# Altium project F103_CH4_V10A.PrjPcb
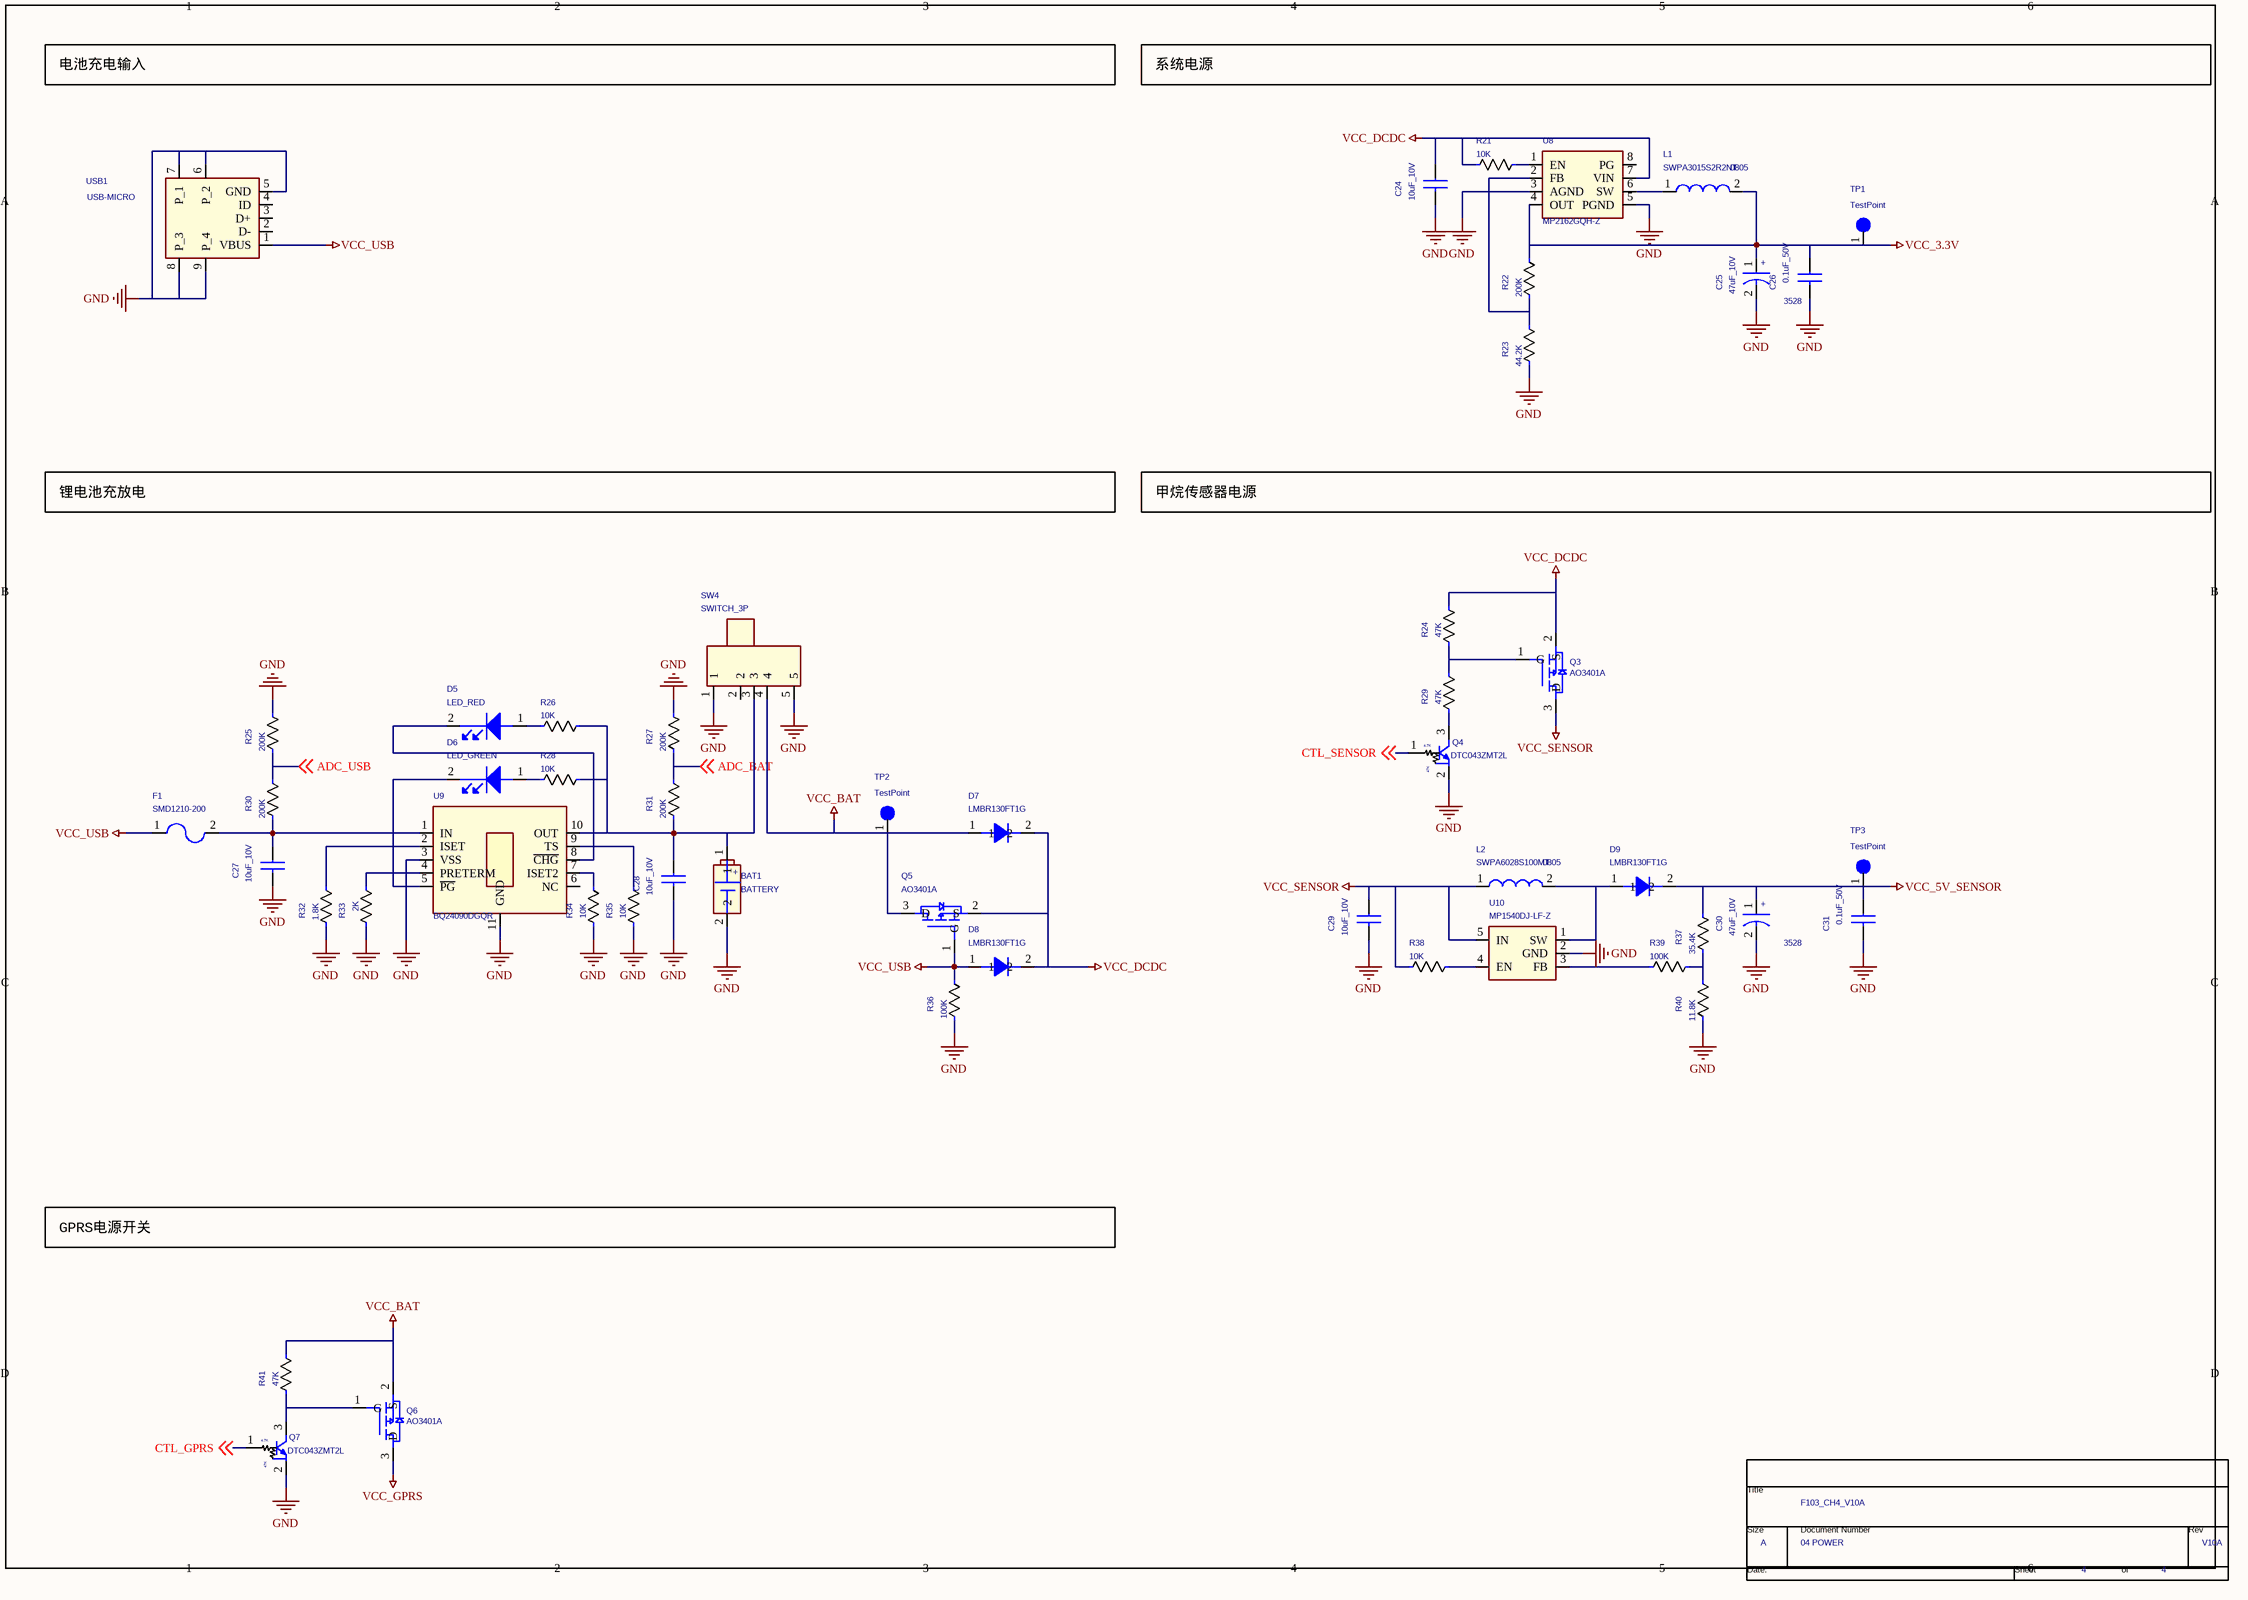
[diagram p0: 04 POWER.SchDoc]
4 sheets, 120 parts. Net scope: global (net labels, ports and power ports of the same name join across sheets).
Board file: F103_CH4_V10A.PcbDoc
Sheets:
  04 POWER.SchDoc
  03 GPRS.SchDoc
  02 MCU&SENSOR.SchDoc
  01 COVER.SchDoc

## Sheet 04 POWER.SchDoc
size 420 x 297 mm

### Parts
(Parts that share a designator on the sheet are numbered #1, #2 ... from top to bottom, then left to right.)
*#1  Page Count: 4  Page Size: A  Title: F103_CH4_V10A  RevCode: V10A  Doc: 04 POWER  (hidden comment: TitleBlock0)  (graphical)
BAT1  BATTERY  [BATTERY]
C24  10uF_10V  [C0603]
C25  47uF_10V  Shape: 3528  [CT_3528_IPC]
C26  0.1uF_50V  [C0603]
C27  10uF_10V  [C0603]
C28  10uF_10V  [C0603]
C29  10uF_10V  [C0603]
C30  47uF_10V  Shape: 3528  [CT_3528_IPC]
C31  0.1uF_50V  [C0603]
D5  LED_RED  [LED0805]
D6  LED_GREEN  [LED0805]
D7  LMBR130FT1G  [SOD123]
D8  LMBR130FT1G  [SOD123]
D9  LMBR130FT1G  [SOD123]
F1  SMD1210-200  [SMD-2920]
L1  SWPA3015S2R2NT  Shape: 0805  [L_0805_IPC]
L2  SWPA6028S100MT  Shape: 0805  [L_0805_IPC]
Q3  AO3401A  [SOT23_GSD]
Q4  DTC043ZMT2L  [SOT-723]
Q5  AO3401A  [SOT23_GSD]
Q6  AO3401A  [SOT23_GSD]
Q7  DTC043ZMT2L  [SOT-723]
R21  10K  [R0603]
R22  200K  [R0603]
R23  44.2K  [R0603]
R24  47K  [R0603]
R25  200K  [R0603]
R26  10K  [R0603]
R27  200K  [R0603]
R28  10K  [R0603]
R29  47K  [R0603]
R30  200K  [R0603]
R31  200K  [R0603]
R32  1.8K  [R0603]
R33  2K  [R0603]
R34  10K  [R0603]
R35  10K  [R0603]
R36  100K  [R0603]
R37  35.4K  [R0603]
R38  10K  [R0603]
R39  100K  [R0603]
R40  11.8K  [R0603]
R41  47K  [R0603]
SW4  SWITCH_3P  [SWITCH_3P]
TP1  TestPoint  [TP-0R75]
TP2  TestPoint  [TP-0R75]
TP3  TestPoint  [TP-0R75]
U8  MP2162GQH-Z  [QFN-8]
U9  BQ24090DGQR  [HVSSOP-10]
U10  MP1540DJ-LF-Z  [TSOT23-5]
USB1  USB-MICRO  [MICROUSB]

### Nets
GND: BAT1.2 C24.2 C25.2 C26.2 C27.2 C28.2 C29.2 C30.2 C31.2 Q4.2 Q7.2 R23.2 R25.1 R27.1 R32.2 R33.2 R34.2 R35.2 R36.2 R40.2 SW4.1 SW4.5 U8.3(AGND) U8.5(PGND) U9.3(VSS) U9.11(GND) U10.2(GND) USB1.5(GND) USB1.6(P_2) USB1.7(P_1) USB1.8(P_3) USB1.9(P_4)
VCC_3.3V: C25.1 C26.1 L1.2(B) R22.1 TP1.1 U8.4(OUT)
VCC_5V_SENSOR: C30.1 C31.1 D9.2 R37.1 TP3.1
VCC_BAT: D7.1 Q5.3(D) Q6.2(S) R41.1 SW4.4 TP2.1
VCC_DCDC: C24.1 D7.2 D8.2 Q3.2(S) Q5.2(S) R21.1 R24.1 U8.7(VIN)
VCC_GPRS: Q6.3(D)
VCC_SENSOR: C29.1 L2.1(A) Q3.3(D) R38.1 U10.5(IN)
VCC_USB: D8.1 F1.1 Q5.1(G) R36.1 USB1.1(VBUS)
ADC_BAT: R27.2 R31.1 ; off-sheet ADC_BAT
ADC_USB: R25.2 R30.1 ; off-sheet ADC_USB
CTL_GPRS: Q7.1 ; off-sheet CTL_GPRS
CTL_SENSOR: Q4.1 ; off-sheet CTL_SENSOR
NetBAT1_1: BAT1.1 C28.1 R26.2 R28.2 R31.2 SW4.3 U9.10(OUT)
NetC27_1: C27.1 F1.2 R30.2 U9.1(IN)
NetD5_1: D5.1(ANODE) R26.1
NetD5_2: D5.2(CATHODE) U9.8(~{CHG})
NetD6_1: D6.1(ANODE) R28.1
NetD6_2: D6.2(CATHODE) U9.5(~{PG})
NetD9_1: D9.1 L2.2(B) U10.1(SW)
NetL1_1: L1.1(A) U8.6(SW)
NetQ3_1: Q3.1(G) R24.2 R29.1
NetQ4_3: Q4.3 R29.2
NetQ6_1: Q6.1(G) Q7.3 R41.2
NetR21_2: R21.2 U8.1(EN)
NetR22_2: R22.2 R23.1 U8.2(FB)
NetR32_1: R32.1 U9.2(ISET)
NetR33_1: R33.1 U9.4(PRETERM)
NetR34_1: R34.1 U9.7(ISET2)
NetR35_1: R35.1 U9.9(TS)
NetR37_2: R37.2 R39.2 R40.1
NetR38_2: R38.2 U10.4(EN)
NetR39_1: R39.1 U10.3(FB)

Not connected (* = marked no-connect by the designer): SW4 2; U8 8(PG); U9 6(NC); USB1 2(D-) 3(D+) 4(ID)

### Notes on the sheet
- 电池充电输入
- 系统电源
- 锂电池充放电
- 甲烷传感器电源
- GPRS电源开关

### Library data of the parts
BAT1 = BATTERY: XHB-2A
C24 C27-C29 = CAP NP_2: CAP,CERM,+/-10%,X7R,0603; Corporation: FH
C25 C30 = TMP_154254: CAP,TAN,TAJB476K010RNJ; Corporation: AVX; GRN: LHR; EP#: P10100000000041; MFGI 2#: KEM: T494B107K006ATH; MFGI 1#: AVX: TPSB107K006R; Board Option: Base
C26 C31 = CAP NP_Dup1: CAP,CERM,50V,+/-10%,X7R,0603; Corporation: FH
D5 = LED_4: LED; vend_part_desc: DIGI-KEY;PANASONIC; Vend_part_no: P525CT-ND;LNJ308G8TRA; BRCMPN: 106336-00; Second_Description: SING DIF; Vendor_Name: DIGI-KEY;VENDOR TO BE DETERMINED; Specs: 0603
D6 = LED_4: LED; BRCMPN: 106336-00; Vend_part_no: P525CT-ND;LNJ308G8TRA; vend_part_desc: DIGI-KEY;PANASONIC; Description 2: SING DIF; Specs: 0603; Vendor_Name: DIGI-KEY;VENDOR TO BE DETERMINED
D7-D9 = DIODE13_0: SURFACE MOUNT SCHOTTKY BARRIER RECTIFIER; Type: DIODE; Corporation: LRC
F1 = FUSE: Corporation: BOURNS
L1 L2 = IND_BEAD_0805_600OHM_1: MFGI 2#: TDK: MMZ2012Y601B; MFGI 1#: MUR: BLM21B601SPT; Board Option: Base; EP#: P11000000000010; GRN: LHR; Corporation: SUNLORD; Type: INDUCTOR
Q3 Q6 = MOS-P_0_Dup1: 30V P-Channel MOSFET; Corporation: AOS; Type: MOS
Q4 Q7 = DTC043ZMT2L: Corporation: ROHM; Type: NPN
Q5 = MOS-P: 30V P-Channel MOSFET; Corporation: AOS; Type: MOS
R21-R41 = R_Generic: RES,1%,0.1W,0603; Mfg #1: KOA SPEER; P/N #1: RK73H1JT1002F; P/N #3: CR10-103J-T; Corporation: FH
TP1-TP3 = TestPoint_0: Note: NI
U8 = MP2162GQH-Z: 2A, 6V, 1.5MHz SYNCHRONOUS STEP-DOWN SWITCHER; Corporation: MPS
U9 = BQ24090: 1A, Single-Input, Single Cell Li-Ion and Li-Pol Battery Charger; Corporation: TI
U10 = MP1540DJ-LF-Z: 1.3MHz, 18V STEP-UP CONVERTER; Corporation: MPS
USB1 = USB-MICRO: Corporation: LC

## Sheet 03 GPRS.SchDoc
size 420 x 297 mm
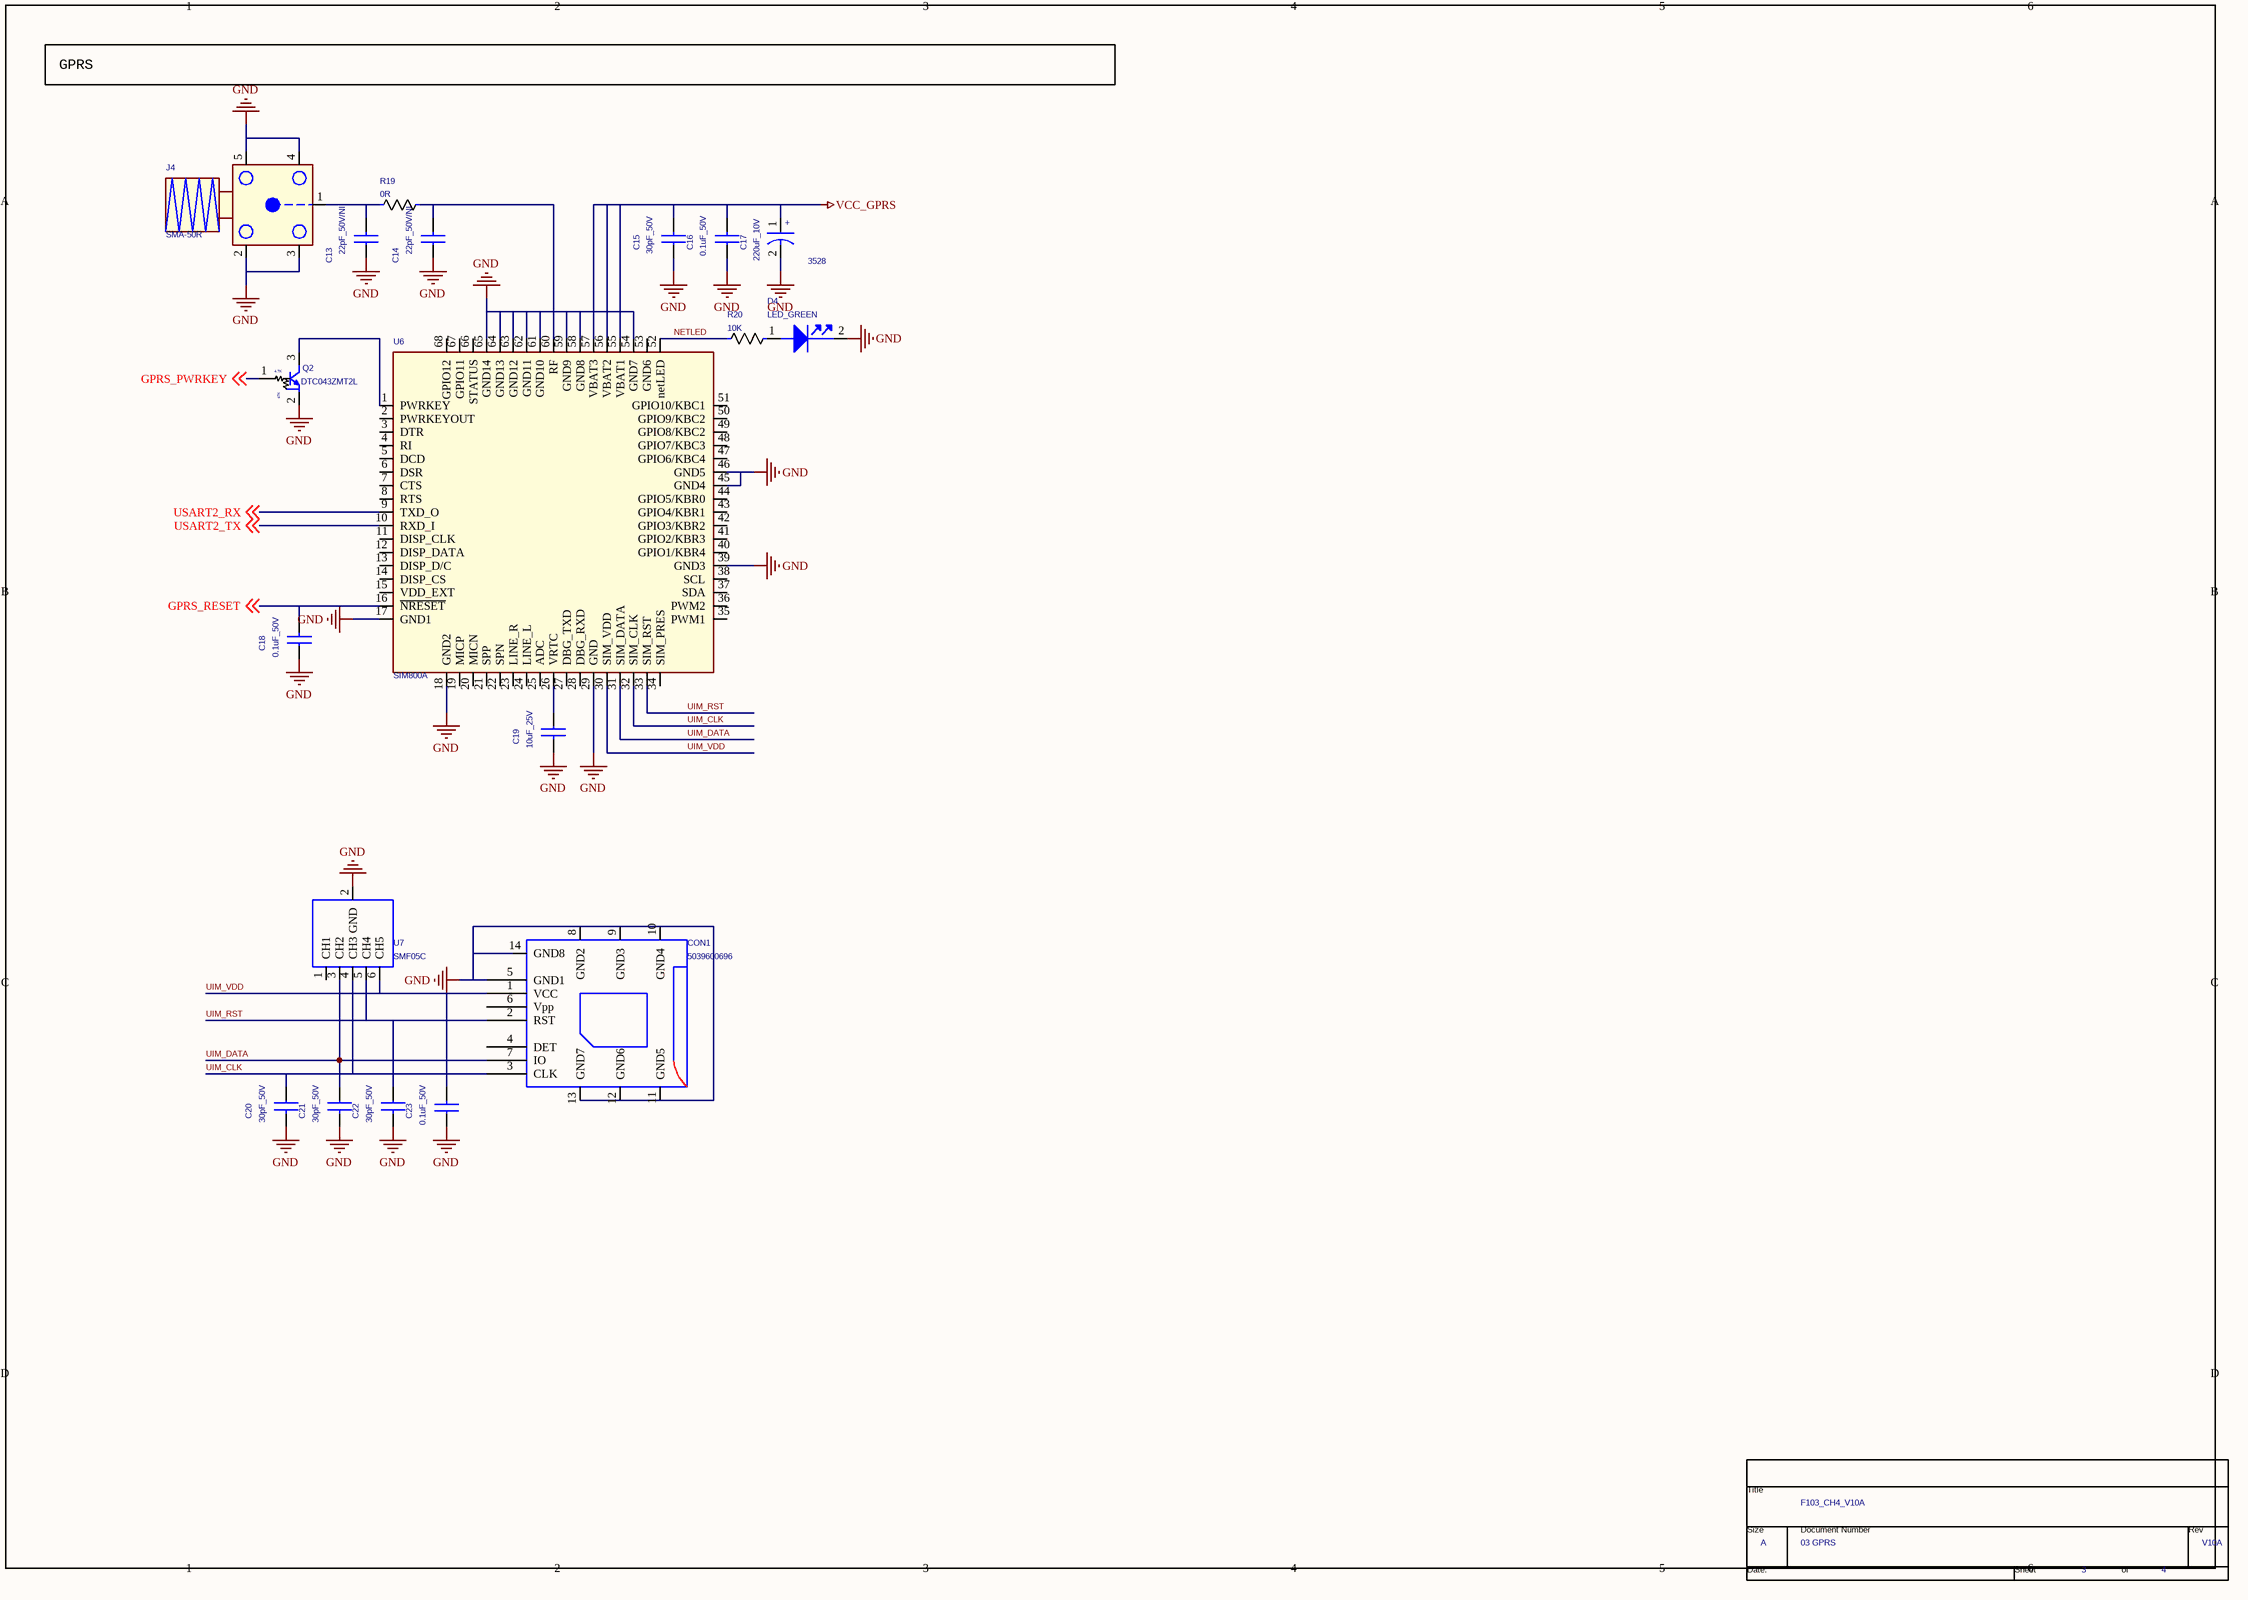
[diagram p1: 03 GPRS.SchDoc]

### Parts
(Parts that share a designator on the sheet are numbered #1, #2 ... from top to bottom, then left to right.)
*#2  Page Count: 4  Page Number: 3  Page Size: A  Title: F103_CH4_V10A  RevCode: V10A  Doc: 03 GPRS  (hidden comment: TitleBlock0)  (graphical)
C13  22pF_50V/NI  [C0603]
C14  22pF_50V/NI  [C0603]
C15  30pF_50V  [C0603]
C16  0.1uF_50V  [C0603]
C17  220uF_10V  Shape: 3528  [CT_3528_IPC]
C18  0.1uF_50V  [C0603]
C19  10uF_25V  [C0805]
C20  30pF_50V  [C0603]
C21  30pF_50V  [C0603]
C22  30pF_50V  [C0603]
C23  0.1uF_50V  [C0603]
CON1  5039600696  [SIM_PUSH]
D4  LED_GREEN  [LED0805]
J4  SMA-50R  [SMA-50R]
Q2  DTC043ZMT2L  [SOT-723]
R19  0R  [R0603]
R20  10K  [R0603]
U6  SIM800A  [SIM800A]
U7  SMF05C  [SOT363]

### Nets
GND: C13.1 C14.1 C15.1 C16.1 C17.2 C18.1 C19.2 C20.2 C21.2 C22.2 C23.1 CON1.5(GND1) CON1.8(GND2) CON1.9(GND3) CON1.10(GND4) CON1.11(GND5) CON1.12(GND6) CON1.13(GND7) CON1.14(GND8) D4.2(CATHODE) J4.2 J4.3 J4.4 J4.5 Q2.2 U6.17(GND1) U6.18(GND2) U6.29(GND) U6.39(GND3) U6.45(GND4) U6.46(GND5) U6.54(GND7) U6.58(GND8) U6.59(GND9) U6.61(GND10) U6.62(GND11) U6.63(GND12) U6.64(GND13) U6.65(GND14) U7.2(GND)
VCC_GPRS: C15.2 C16.2 C17.1 U6.55(VBAT1) U6.56(VBAT2) U6.57(VBAT3)
GPRS_PWRKEY: Q2.1 ; off-sheet GPRS_PWRKEY
GPRS_RESET: C18.2 U6.16(~{NRESET}) ; off-sheet GPRS_RESET
NETLED: R20.1 U6.52(netLED)
UIM_CLK: C20.1 CON1.3(CLK) U6.32(SIM_CLK) U7.4(CH3)
UIM_DATA: C21.1 CON1.7(IO) U6.31(SIM_DATA) U7.3(CH2)
UIM_RST: C22.1 CON1.2(RST) U6.33(SIM_RST) U7.5(CH4)
UIM_VDD: C23.2 CON1.1(VCC) U6.30(SIM_VDD) U7.6(CH5)
USART2_RX: U6.9(TXD_O) ; off-sheet USART2_RX
USART2_TX: U6.10(RXD_I) ; off-sheet USART2_TX
NetC13_2: C13.2 J4.1 R19.1
NetC14_2: C14.2 R19.2 U6.60(RF)
NetC19_1: C19.1 U6.26(VRTC)
NetD4_1: D4.1(ANODE) R20.2
NetQ2_3: Q2.3 U6.1(PWRKEY)

Not connected (* = marked no-connect by the designer): CON1 4(DET) 6(Vpp); U6 2(PWRKEYOUT) 3(DTR) 4(RI) 5(DCD) 6(DSR) 7(CTS) 8(RTS) 11(DISP_CLK) 12(DISP_DATA) 13(DISP_D/C) 14(DISP_CS) 15(VDD_EXT) 19(MICP) 20(MICN) 21(SPP) 22(SPN) 23(LINE_R) 24(LINE_L) 25(ADC) 27(DBG_TXD) 28(DBG_RXD) 34(SIM_PRES) 35(PWM1) 36(PWM2) 37(SDA) 38(SCL) 40(GPIO1/KBR4) 41(GPIO2/KBR3) 42(GPIO3/KBR2) 43(GPIO4/KBR1) 44(GPIO5/KBR0) 47(GPIO6/KBC4) 48(GPIO7/KBC3) 49(GPIO8/KBC2) 50(GPIO9/KBC2) 51(GPIO10/KBC1) 53(GND6) 66(STATUS) 67(GPIO11) 68(GPIO12); U7 1(CH1)

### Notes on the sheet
- GPRS

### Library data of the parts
C13-C16 C18 C20-C23 = CAP NP_2: as C24 on sheet 04 POWER
C17 = TMP_154254: CAP,TAN,TAJE227M010RNJ; Corporation: AVX; GRN: LHR; EP#: P10100000000041; MFGI 2#: KEM: T494B107K006ATH; MFGI 1#: AVX: TPSB107K006R; Board Option: Base
C19 = CAP NP_0: CAP,CERM,+/-10%,X5R,0805; Corporation: FH
CON1 = SIM_Card_2: SIM_PUSH; Corporation: MOLEX
D4 = LED_4: vend_part_desc: DIGI-KEY;PANASONIC; Vend_part_no: P525CT-ND;LNJ308G8TRA; BRCMPN: 106336-00; Second_Description: SING DIF; Vendor_Name: DIGI-KEY;VENDOR TO BE DETERMINED; Specs: 0603; Type: LED
J4 = SMA-50R_0: SMA-50R-DIP
Q2 = DTC043ZMT2L: Corporation: ROHM; Type: NPN
R19 R20 = R_Generic: as R21 on sheet 04 POWER
U6 = SIM800A: GPRS MODULA; Corporation: SIMCOM
U7 = SMF05CT1G: 5-Line TVS Array; Corporation: ON

## Sheet 02 MCU&SENSOR.SchDoc
size 420 x 297 mm
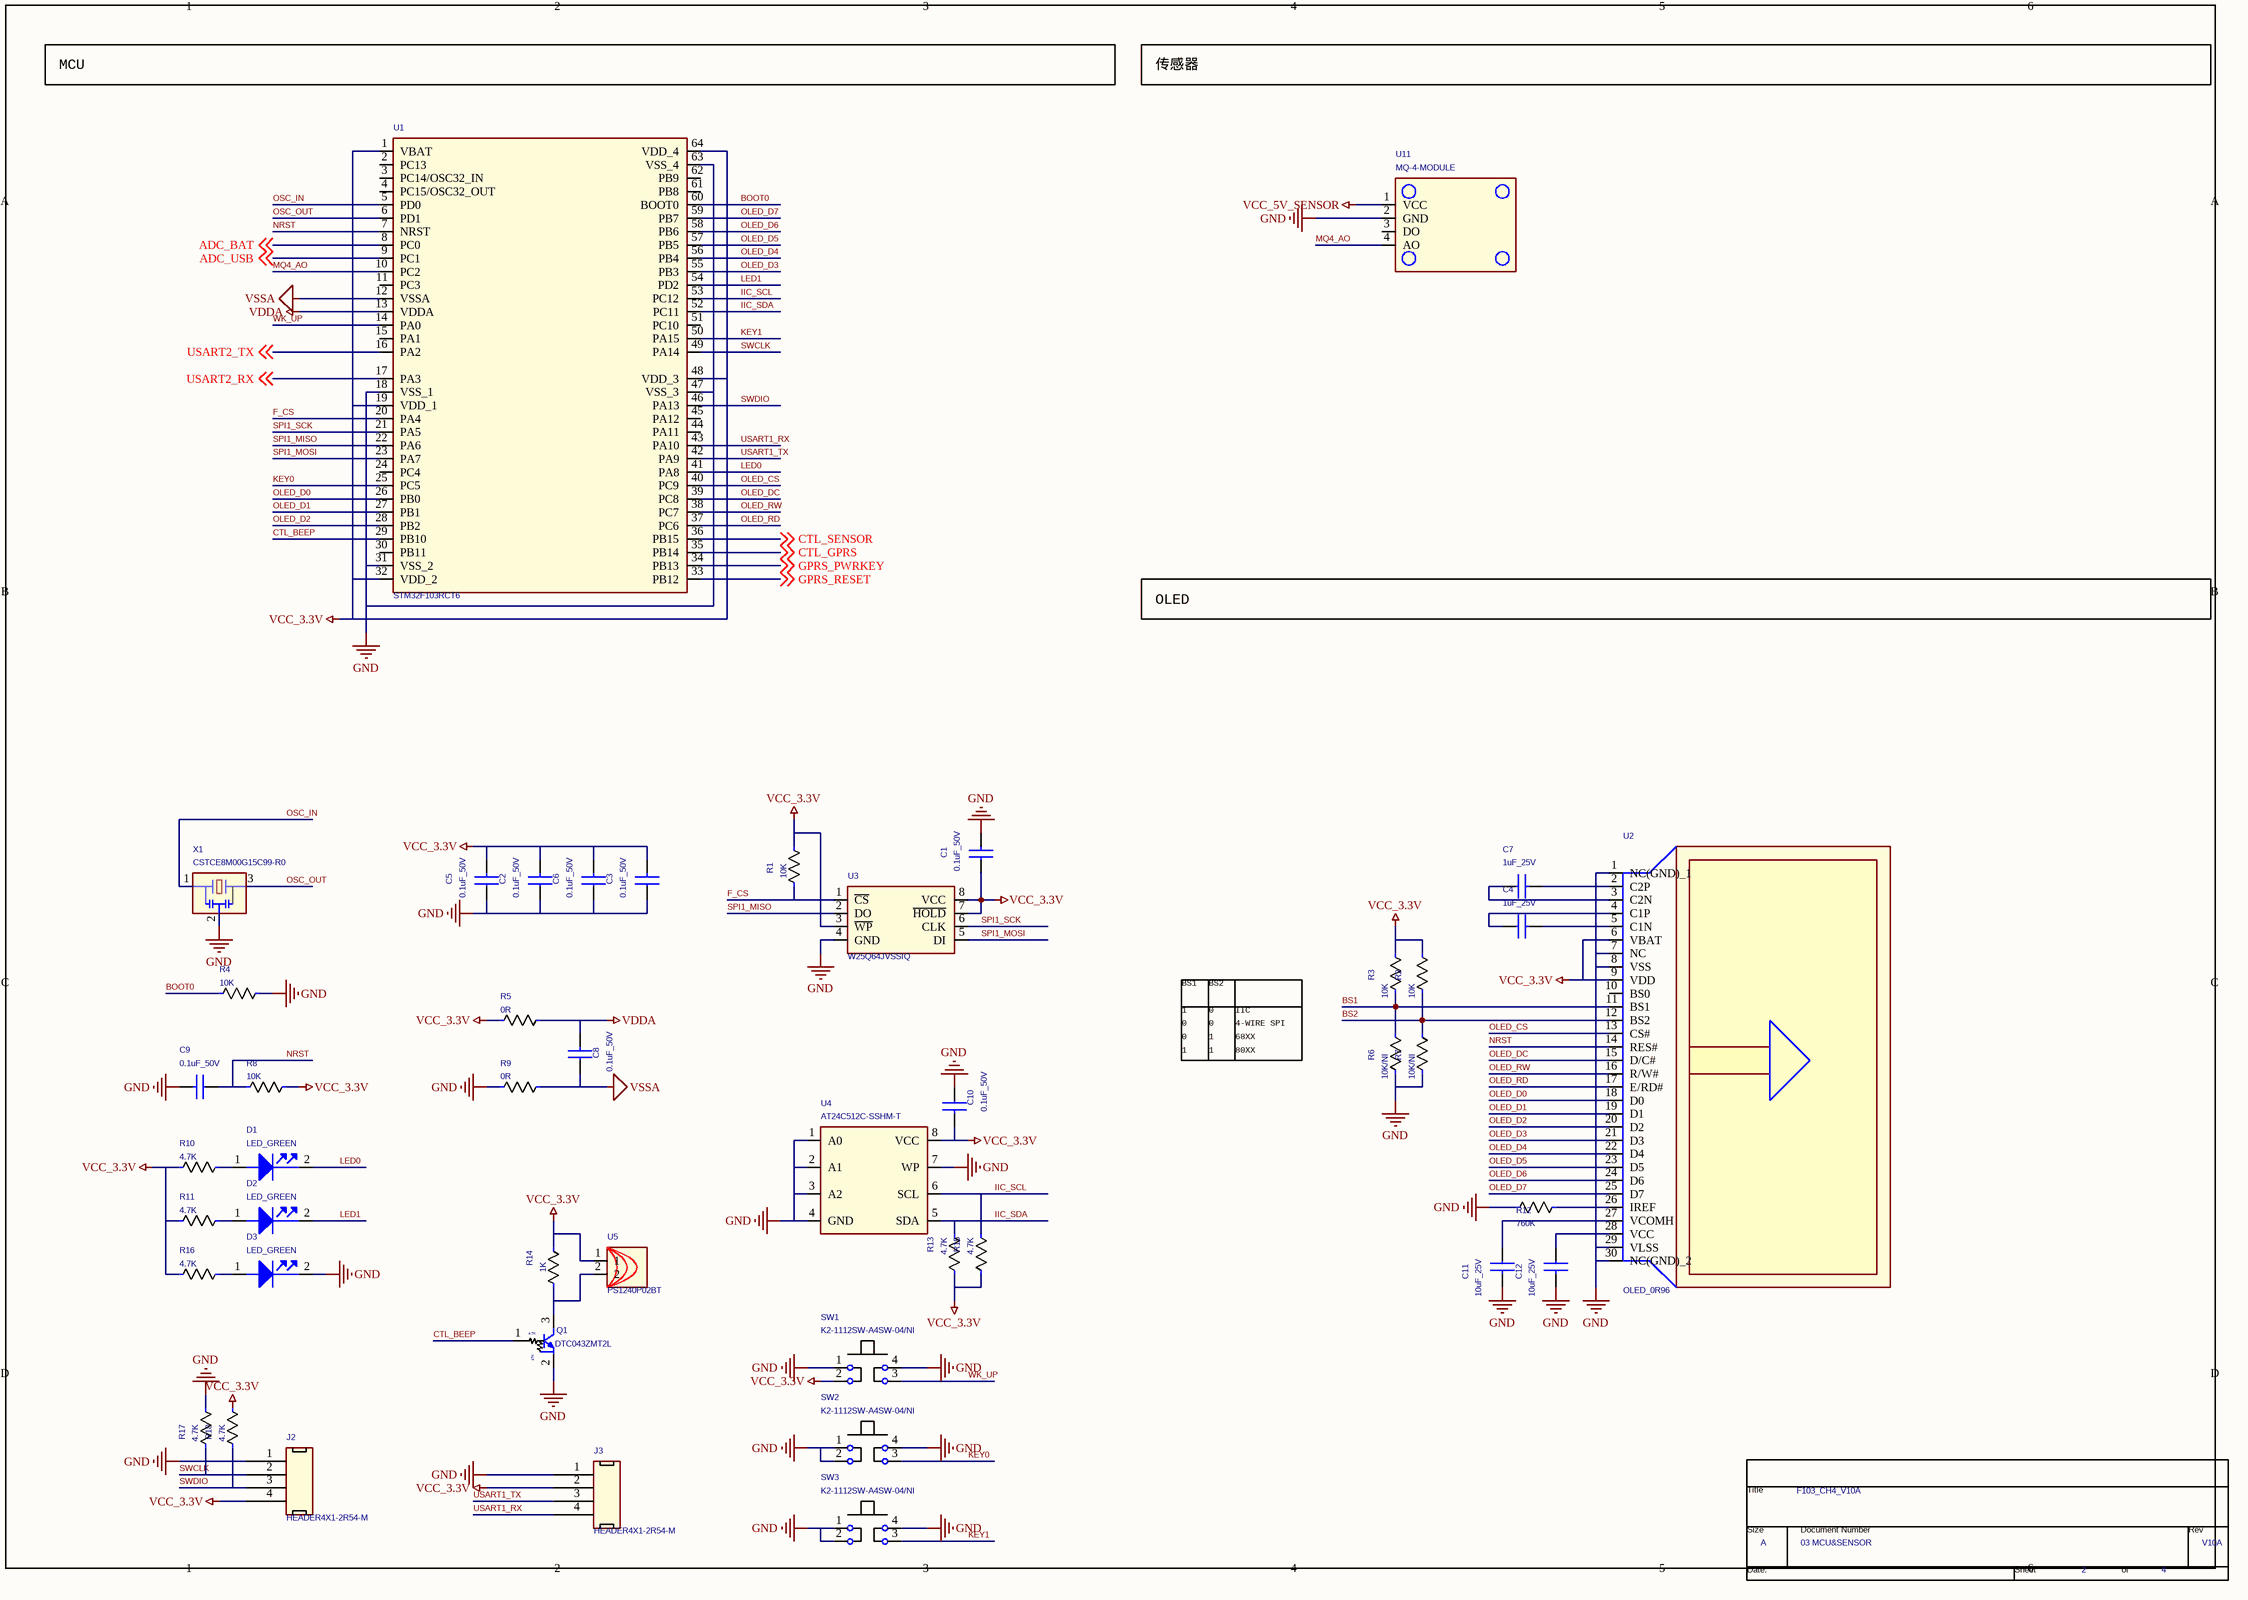
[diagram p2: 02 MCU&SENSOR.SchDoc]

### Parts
(Parts that share a designator on the sheet are numbered #1, #2 ... from top to bottom, then left to right.)
*#3  Page Count: 4  Page Number: 2  Page Size: A  Title: F103_CH4_V10A  RevCode: V10A  Doc: 03 MCU&SENSOR  (hidden comment: TitleBlock0)  (graphical)
C1  0.1uF_50V  [C0603]
C2  0.1uF_50V  [C0603]
C3  0.1uF_50V  [C0603]
C4  1uF_25V  [C0603]
C5  0.1uF_50V  [C0603]
C6  0.1uF_50V  [C0603]
C7  1uF_25V  [C0603]
C8  0.1uF_50V  [C0603]
C9  0.1uF_50V  [C0603]
C10  0.1uF_50V  [C0603]
C11  10uF_25V  [C0805]
C12  10uF_25V  [C0805]
D1  LED_GREEN  [LED0805]
D2  LED_GREEN  [LED0805]
D3  LED_GREEN  [LED0805]
J2  HEADER4X1-2R54-M  [HEADER4X1-2R54-M]
J3  HEADER4X1-2R54-M  [HEADER4X1-2R54-M]
Q1  DTC043ZMT2L  [SOT-723]
R1  10K  [R0603]
R2  10K  [R0603]
R3  10K  [R0603]
R4  10K  [R0603]
R5  0R  [R0603]
R6  10K/NI  [R0603]
R7  10K/NI  [R0603]
R8  10K  [R0603]
R9  0R  [R0603]
R10  4.7K  [R0603]
R11  4.7K  [R0603]
R12  760K  [R0603]
R13  4.7K  [R0603]
R14  1K  [R0603]
R15  4.7K  [R0603]
R16  4.7K  [R0603]
R17  4.7K  [R0603]
R18  4.7K  [R0603]
SW1  K2-1112SW-A4SW-04/NI  [SPST]
SW2  K2-1112SW-A4SW-04/NI  [SPST]
SW3  K2-1112SW-A4SW-04/NI  [SPST]
U1  STM32F103RCT6  [QFP-64]
U2  OLED_0R96  [OLED_0r96]
U3  W25Q64JVSSIQ  [SO-8-W]
U4  AT24C512C-SSHM-T  [SOIC8]
U5  PS1240P02BT  [PS1240P02BT]
U11  MQ-4-MODULE  [MQ-4-MODULE]
X1  CSTCE8M00G15C99-R0  [XTAL_5032]

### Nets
GND: C1.2 C2.1 C3.1 C5.1 C6.1 C9.2 C10.1 C11.2 C12.2 D3.2(CATHODE) J2.1 J3.1 Q1.2 R4.2 R6.1 R7.1 R9.2 R12.1 R17.1 SW1.1 SW1.4 SW2.1 SW2.2 SW2.4 SW3.1 SW3.2 SW3.4 U1.18(VSS_1) U1.31(VSS_2) U1.47(VSS_3) U1.63(VSS_4) U2.1(NC(GND)_1) U2.7(NC) U2.8(VSS) U2.29(VLSS) U2.30(NC(GND)_2) U3.4(GND) U4.1(A0) U4.2(A1) U4.3(A2) U4.4(GND) U4.7(WP) U11.2(GND) X1.2
VCC_3.3V: C1.1 C2.2 C3.2 C5.2 C6.2 C10.2 J2.4 J3.2 R1.1 R2.2 R3.2 R5.2 R8.1 R10.1 R11.1 R13.2 R14.1 R15.2 R16.1 R18.1 SW1.2 U1.1(VBAT) U1.19(VDD_1) U1.32(VDD_2) U1.48(VDD_3) U1.64(VDD_4) U2.6(VBAT) U2.9(VDD) U3.3(~{WP}) U3.7(~{HOLD}) U3.8(VCC) U4.8(VCC) U5.1
VCC_5V_SENSOR: U11.1(VCC)
VDDA: C8.2 R5.1 U1.13(VDDA)
VSSA: C8.1 R9.1 U1.12(VSSA)
ADC_BAT: U1.8(PC0) ; off-sheet ADC_BAT
ADC_USB: U1.9(PC1) ; off-sheet ADC_USB
BOOT0: R4.1 U1.60(BOOT0)
BS1: R3.1 R6.2 U2.11(BS1)
BS2: R2.1 R7.2 U2.12(BS2)
CTL_BEEP: Q1.1 U1.29(PB10)
CTL_GPRS: U1.35(PB14) ; off-sheet CTL_GPRS
CTL_SENSOR: U1.36(PB15) ; off-sheet CTL_SENSOR
F_CS: R1.2 U1.20(PA4) U3.1(~{CS})
GPRS_PWRKEY: U1.34(PB13) ; off-sheet GPRS_PWRKEY
GPRS_RESET: U1.33(PB12) ; off-sheet GPRS_RESET
IIC_SCL: R15.1 U1.53(PC12) U4.6(SCL)
IIC_SDA: R13.1 U1.52(PC11) U4.5(SDA)
KEY0: SW2.3 U1.25(PC5)
KEY1: SW3.3 U1.50(PA15)
LED0: D1.2(CATHODE) U1.41(PA8)
LED1: D2.2(CATHODE) U1.54(PD2)
MQ4_AO: U1.10(PC2) U11.4(AO)
NRST: C9.1 R8.2 U1.7(NRST) U2.14(RES#)
OLED_CS: U1.40(PC9) U2.13(CS#)
OLED_D0: U1.26(PB0) U2.18(D0)
OLED_D1: U1.27(PB1) U2.19(D1)
OLED_D2: U1.28(PB2) U2.20(D2)
OLED_D3: U1.55(PB3) U2.21(D3)
OLED_D4: U1.56(PB4) U2.22(D4)
OLED_D5: U1.57(PB5) U2.23(D5)
OLED_D6: U1.58(PB6) U2.24(D6)
OLED_D7: U1.59(PB7) U2.25(D7)
OLED_DC: U1.39(PC8) U2.15(D/C#)
OLED_RD: U1.37(PC6) U2.17(E/RD#)
OLED_RW: U1.38(PC7) U2.16(R/W#)
OSC_IN: U1.5(PD0) X1.1
OSC_OUT: U1.6(PD1) X1.3
SPI1_MISO: U1.22(PA6) U3.2(DO)
SPI1_MOSI: U1.23(PA7) U3.5(DI)
SPI1_SCK: U1.21(PA5) U3.6(CLK)
SWCLK: J2.2 R17.2 U1.49(PA14)
SWDIO: J2.3 R18.2 U1.46(PA13)
USART1_RX: J3.4 U1.43(PA10)
USART1_TX: J3.3 U1.42(PA9)
USART2_RX: U1.17(PA3) ; off-sheet USART2_RX
USART2_TX: U1.16(PA2) ; off-sheet USART2_TX
WK_UP: SW1.3 U1.14(PA0)
NetC4_1: C4.1 U2.4(C1P)
NetC4_2: C4.2 U2.5(C1N)
NetC7_1: C7.1 U2.3(C2N)
NetC7_2: C7.2 U2.2(C2P)
NetC11_1: C11.1 U2.27(VCOMH)
NetC12_1: C12.1 U2.28(VCC)
NetD1_1: D1.1(ANODE) R10.2
NetD2_1: D2.1(ANODE) R11.2
NetD3_1: D3.1(ANODE) R16.2
NetQ1_3: Q1.3 R14.2 U5.2
NetR12_2: R12.2 U2.26(IREF)

Not connected (* = marked no-connect by the designer): U1 2(PC13) 3(PC14/OSC32_IN) 4(PC15/OSC32_OUT) 11(PC3) 15(PA1) 24(PC4) 30(PB11) 44(PA11) 45(PA12) 51(PC10) 61(PB8) 62(PB9); U2 10(BS0); U11 3(DO)

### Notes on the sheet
- MCU
- 传感器
- OLED
- BS1
- BS2
- 1
- 0
- 68XX
- 80XX
- IIC
- 4-WIRE SPI

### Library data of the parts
C1-C8 = CAP NP_2: as C24 on sheet 04 POWER
C9 = CAP NP: CAP,CERM,+/-10%,X7R,0603; Corporation: FH
C10 = CAP NP_3: CAP,CERM,+/-10%,X7R,0603; Corporation: FH
C11 C12 = CAP NP_2: CAP,CERM,+/-10%,X5R,0805; Corporation: FH
D1-D3 = LED_4: BRCMPN: 106336-00; Vend_part_no: P525CT-ND;LNJ308G8TRA; vend_part_desc: DIGI-KEY;PANASONIC; Description 2: SING DIF; Specs: 0603; Vendor_Name: DIGI-KEY;VENDOR TO BE DETERMINED; Type: LED
J2 J3 = CONN RCPT 4_Dup1: Corporation: NEXTRON
Q1 = DTC043ZMT2L: Corporation: ROHM; Type: NPN
R1-R18 = R_Generic: as R21 on sheet 04 POWER
SW1-SW3 = SWITCH-SPST-4P: K2-1112SW-A4SW-04; Note: NI
U1 = STM32F103RxT6: ST Cortex-m3 MCU
U2 = OLED_0
U3 = W25Qxx: 3V 64M-BIT SPI FLASH; Corporation: WINBOND
U4 = AT24C512: Corporation: MICROCHIP
U5 = PS1240P02BT: Corporation: TDK
U11 = MQ-4-MODULE: Corporation: WINSEN
X1 = XTAL_5032_0: Corporation: muRata

## Sheet 01 COVER.SchDoc
size 420 x 297 mm
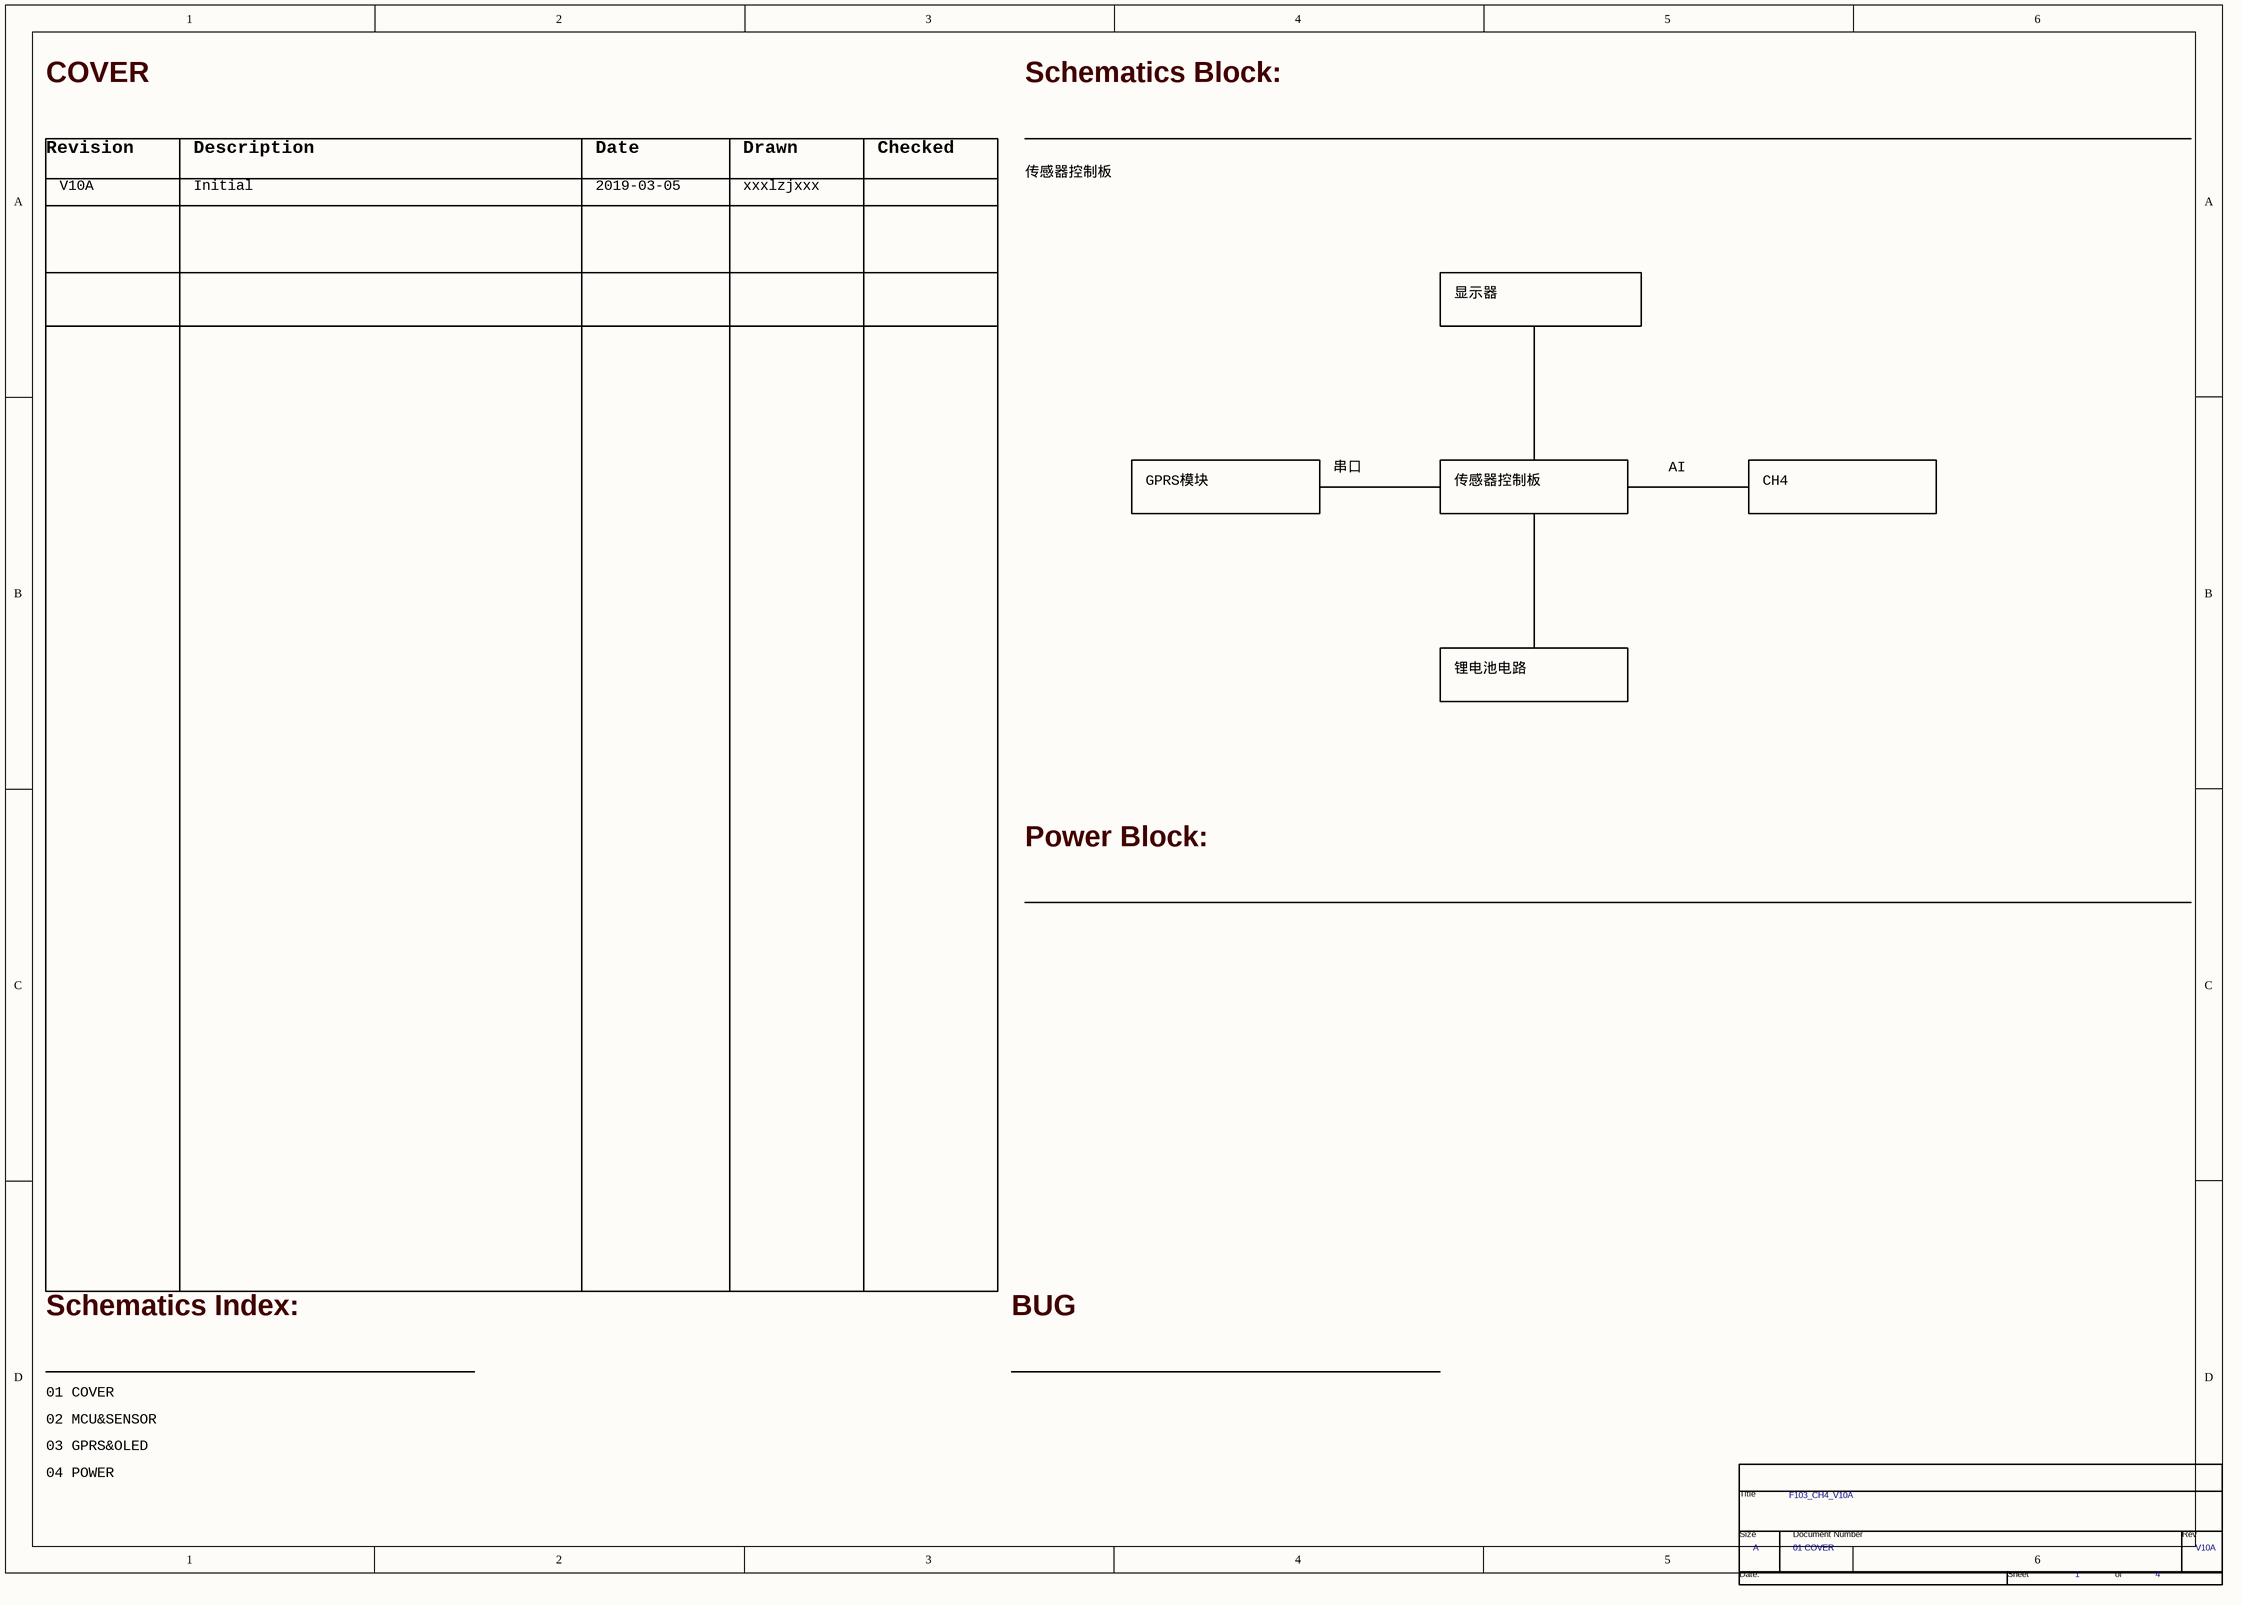
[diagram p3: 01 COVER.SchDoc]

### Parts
(Parts that share a designator on the sheet are numbered #1, #2 ... from top to bottom, then left to right.)
*#4  Page Count: 4  Page Number: 1  Page Size: A  Title: F103_CH4_V10A  RevCode: V10A  Doc: 01 COVER  (hidden comment: TitleBlock0)  (graphical)

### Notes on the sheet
- COVER
- Schematics Block:
- Revision
- V10A
- Description
- Initial
- Date
- 2019-03-05
- Drawn
- xxxlzjxxx
- Checked
- 传感器控制板
- 显示器
- GPRS模块
- 串口
- AI
- CH4
- 锂电池电路
- Power Block:
- Schematics Index:
- BUG
- 01 COVER
- 03 GPRS&OLED
- 02 MCU&SENSOR
- 04 POWER

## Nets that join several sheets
GND: 04 POWER (32 pins), 03 GPRS (40 pins), 02 MCU&SENSOR (44 pins)
VCC_3.3V: 04 POWER (6 pins), 02 MCU&SENSOR (33 pins)
VCC_5V_SENSOR: 04 POWER (5 pins), 02 MCU&SENSOR (U11.1)
VCC_GPRS: 04 POWER (Q6.3), 03 GPRS (6 pins)
ADC_BAT: 04 POWER (R27.2 R31.1), 02 MCU&SENSOR (U1.8)
ADC_USB: 04 POWER (R25.2 R30.1), 02 MCU&SENSOR (U1.9)
CTL_GPRS: 04 POWER (Q7.1), 02 MCU&SENSOR (U1.35)
CTL_SENSOR: 04 POWER (Q4.1), 02 MCU&SENSOR (U1.36)
GPRS_PWRKEY: 03 GPRS (Q2.1), 02 MCU&SENSOR (U1.34)
GPRS_RESET: 03 GPRS (C18.2 U6.16), 02 MCU&SENSOR (U1.33)
USART2_RX: 03 GPRS (U6.9), 02 MCU&SENSOR (U1.17)
USART2_TX: 03 GPRS (U6.10), 02 MCU&SENSOR (U1.16)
